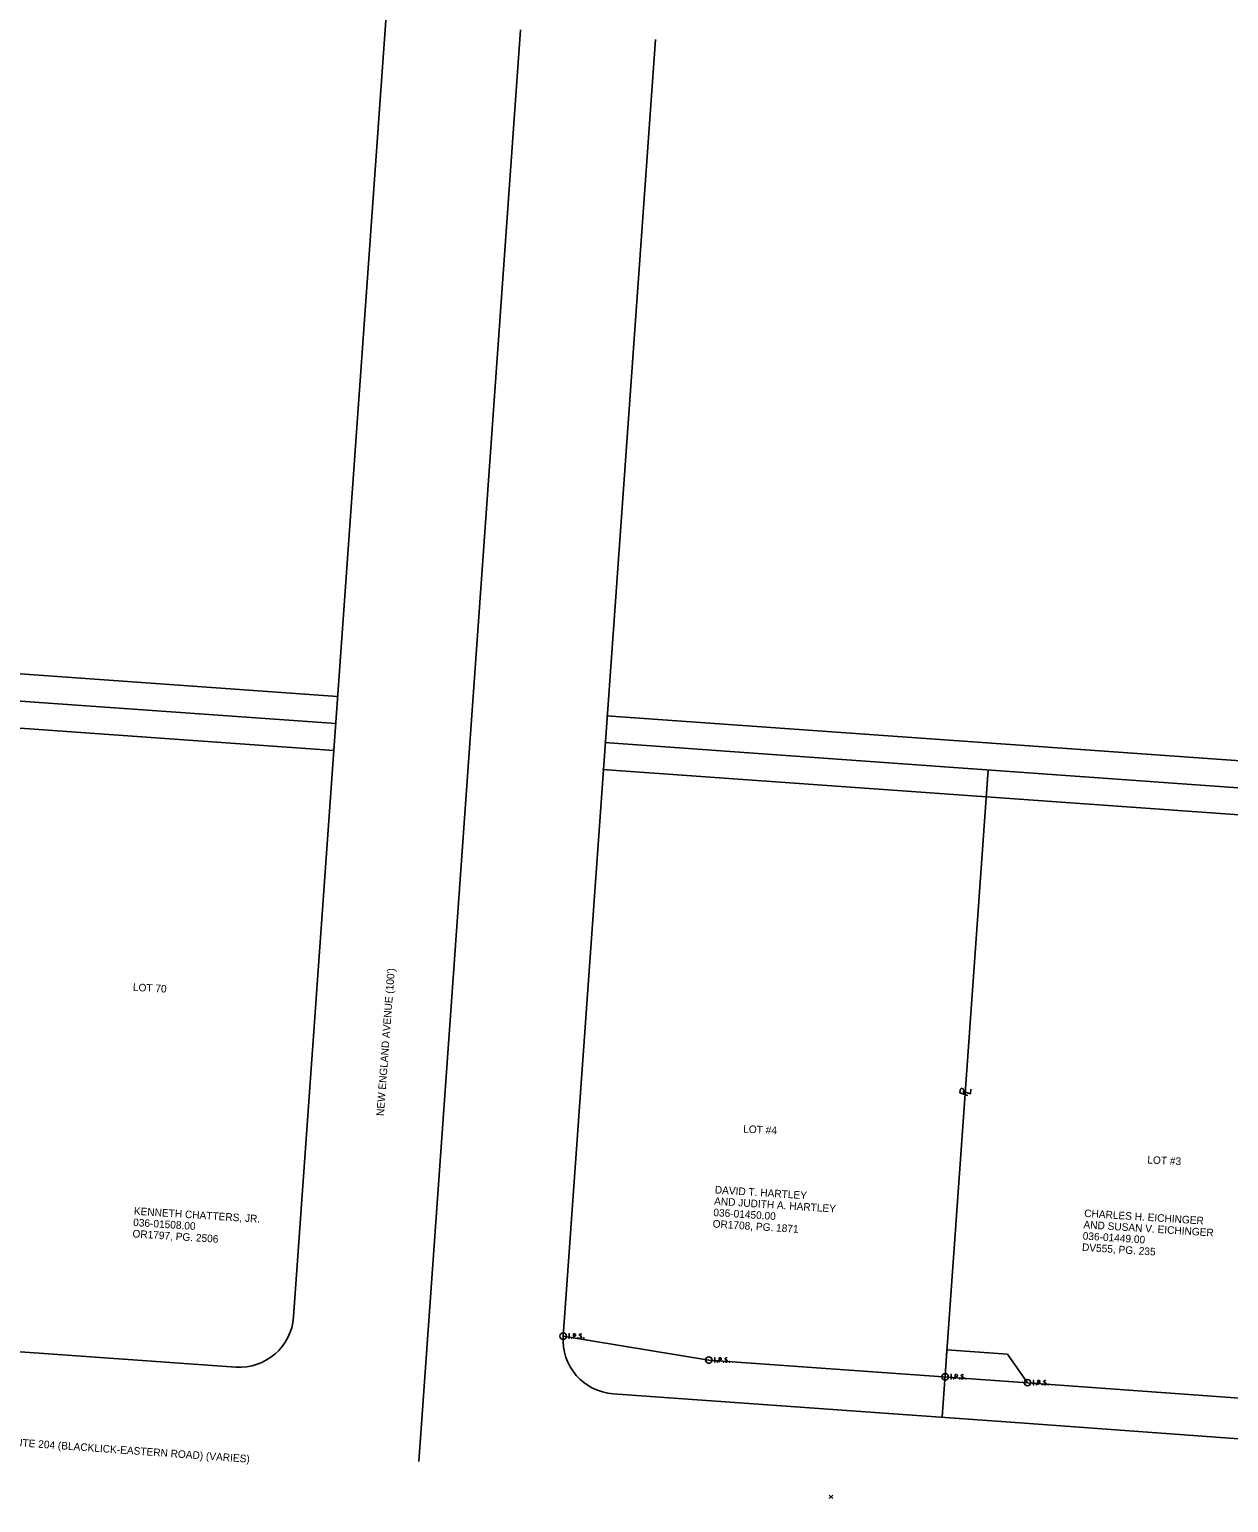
# Model space of a CAD drawing. Extents: x 1898254 to 1901377, y 701554 to 704886.
# Drawn here: x 1899450 to 1899893, y 703230 to 703775 of the extents above; entities that cross this region are included whole.
import ezdxf

# ---------------------------------------------------------------- set-up
doc = ezdxf.new("R2010")
doc.units = 0
for name, color, linetype in [('_CIVIL_CONSTRUCTION', 7, 'Continuous'), ('DV_X_Property_Line', 7, 'Continuous'), ('DV_X_Text', 7, 'Continuous'), ('PF_X_Ground_Line', 7, 'Continuous'), ('RW_X_CL', 7, 'Continuous'), ('RW_X_Esmt_U', 7, 'Continuous'), ('RW_X_Fee_RW', 7, 'Continuous'), ('RW_X_Text', 7, 'Continuous'), ('SC_Scratch2', 7, 'Continuous'), ('SC_Scratch5', 7, 'Continuous'), ('SV_P_Mon_Cells_Set', 7, 'Continuous'), ('SV_X_Random_Point', 7, 'Continuous')]:
    doc.layers.add(name, color=color, linetype=linetype)

msp = doc.modelspace()

# ---------------------------------------------------------------- linework, layer by layer
at = {"layer": '_CIVIL_CONSTRUCTION'}
msp.add_lwpolyline([(1899788.53, 703276.89), (1899789.24, 703286.86), (1899811.58, 703285.28), (1899819.04, 703274.72)], dxfattribs=at)
at = {"layer": 'DV_X_Property_Line'}
for p, q in [((1899563.1, 703518.49), (1898995.75, 703558.83)), ((1900230.14, 703471.05), (1899662.55, 703511.42)), ((1899804.49, 703501.32), (1899787.47, 703261.93)), ((1899795.34, 703381.45), (1899795.43, 703382.74)), ((1899796.02, 703382.2), (1899796.02, 703382.2))]:
    msp.add_line(p, q, dxfattribs=at)
for points in [[(1899796.9, 703380.92), (1899794, 703381.91), (1899794.07, 703382.94)], [(1899795.08, 703382.54), (1899797.98, 703381.54), (1899798.1, 703383.28)]]:
    msp.add_lwpolyline(points, dxfattribs=at)
msp.add_arc((1899794.75, 703382.79), 0.69, 356.4035, 167.2606, dxfattribs=at)
at = {"layer": 'PF_X_Ground_Line'}
msp.add_lwpolyline([(1899647.24, 703291.95), (1899701.15, 703283.1), (1899819.04, 703274.72), (1899960.56, 703264.37), (1900071.43, 703251.26), (1900129.75, 703246.99), (1900212.52, 703235.93), (1900212.15, 703230.94)], dxfattribs=at)
at = {"layer": 'RW_X_CL'}
msp.add_line((1899631.47, 703775.05), (1899593.82, 703245.62), dxfattribs=at)
at = {"layer": 'RW_X_Esmt_U'}
msp.add_line((1899188.39, 703555.16), (1899563.81, 703528.46), dxfattribs=at)
for points in [[(1899139.33, 703489.9), (1899174.08, 703536.13), (1899562.39, 703508.51)], [(1899663.26, 703521.39), (1900220.92, 703481.74), (1900223.2, 703512.15)], [(1899661.84, 703501.44), (1900219.42, 703461.79), (1900202.18, 703231.69)]]:
    msp.add_lwpolyline(points, dxfattribs=at)
at = {"layer": 'RW_X_Fee_RW'}
for p, q in [((1899547.5, 703299.04), (1899581.6, 703778.6)), ((1899681.35, 703771.51), (1899647.24, 703291.95)), ((1898630.14, 703344.22), (1899526.13, 703280.51)), ((1899665.78, 703270.58), (1899817.89, 703259.76)), ((1899817.89, 703259.76), (1900604.1, 703202.29))]:
    msp.add_line(p, q, dxfattribs=at)
for centre, start, end in [((1899527.55, 703300.46), 265.9325, 355.9325), ((1899667.19, 703290.53), 175.9325, 265.9325)]:
    msp.add_arc(centre, 20, start, end, dxfattribs=at)
at = {"layer": 'SC_Scratch2'}
msp.add_circle((1899815.76, 703229.84), 1561.35, dxfattribs=at)
at = {"layer": 'SC_Scratch5'}
for p, q in [((1899547.5, 703299.04), (1899581.6, 703778.6)), ((1899681.35, 703771.51), (1899647.24, 703291.95)), ((1898630.14, 703344.22), (1899526.13, 703280.51)), ((1899665.78, 703270.58), (1899817.89, 703259.76)), ((1899817.89, 703259.76), (1900604.1, 703202.29))]:
    msp.add_line(p, q, dxfattribs=at)
for points in [[(1899647.24, 703291.95), (1899701.15, 703283.1), (1899819.04, 703274.72), (1899960.56, 703264.37), (1900071.43, 703251.26), (1900129.75, 703246.99), (1900212.52, 703235.93), (1900212.15, 703230.94)], [(1899788.53, 703276.89), (1899789.24, 703286.86), (1899811.58, 703285.28), (1899819.04, 703274.72)]]:
    msp.add_lwpolyline(points, dxfattribs=at)
for centre, start, end in [((1899527.55, 703300.46), 265.9325, 355.9325), ((1899667.19, 703290.53), 175.9325, 265.9325)]:
    msp.add_arc(centre, 20, start, end, dxfattribs=at)
at = {"layer": 'SV_P_Mon_Cells_Set'}
for points in [[(1899649.26, 703292.75), (1899649.62, 703292.75)], [(1899649.44, 703291.15), (1899649.44, 703292.75)], [(1899651.01, 703291.15), (1899651.01, 703292.75), (1899651.53, 703292.75), (1899651.59, 703292.74), (1899651.67, 703292.71), (1899651.7, 703292.69), (1899651.73, 703292.66), (1899651.78, 703292.6), (1899651.81, 703292.54), (1899651.83, 703292.44), (1899651.83, 703292.28), (1899651.82, 703292.23), (1899651.8, 703292.16), (1899651.75, 703292.07), (1899651.71, 703292.03), (1899651.68, 703292.01), (1899651.62, 703291.98), (1899651.53, 703291.97), (1899651.01, 703291.97)], [(1899654.01, 703292.64), (1899653.99, 703292.66), (1899653.96, 703292.69), (1899653.86, 703292.73), (1899653.74, 703292.75), (1899653.65, 703292.75), (1899653.62, 703292.75), (1899653.47, 703292.71), (1899653.35, 703292.64), (1899653.28, 703292.54), (1899653.25, 703292.44), (1899653.25, 703292.36), (1899653.28, 703292.26), (1899653.36, 703292.17), (1899653.97, 703291.79), (1899654.03, 703291.74), (1899654.05, 703291.69), (1899654.07, 703291.62), (1899654.07, 703291.54), (1899654.06, 703291.47), (1899654.05, 703291.42), (1899654.03, 703291.35), (1899654, 703291.3), (1899653.98, 703291.26), (1899653.95, 703291.23), (1899653.92, 703291.2), (1899653.87, 703291.18), (1899653.84, 703291.16), (1899653.74, 703291.15), (1899653.58, 703291.15), (1899653.49, 703291.18), (1899653.34, 703291.26), (1899653.25, 703291.34)], [(1899649.26, 703291.15), (1899649.62, 703291.15)], [(1899650.4, 703291.36), (1899650.45, 703291.36), (1899650.49, 703291.34), (1899650.52, 703291.29), (1899650.52, 703291.23), (1899650.49, 703291.18), (1899650.45, 703291.15), (1899650.4, 703291.15), (1899650.37, 703291.18), (1899650.33, 703291.23), (1899650.33, 703291.29), (1899650.37, 703291.34), (1899650.4, 703291.36)], [(1899652.65, 703291.36), (1899652.7, 703291.36), (1899652.74, 703291.34), (1899652.77, 703291.29), (1899652.77, 703291.23), (1899652.74, 703291.18), (1899652.7, 703291.15), (1899652.65, 703291.15), (1899652.61, 703291.18), (1899652.58, 703291.23), (1899652.58, 703291.29), (1899652.61, 703291.34), (1899652.65, 703291.36)], [(1899654.83, 703291.36), (1899654.89, 703291.36), (1899654.92, 703291.34), (1899654.95, 703291.29), (1899654.95, 703291.23), (1899654.92, 703291.18), (1899654.89, 703291.15), (1899654.83, 703291.15), (1899654.8, 703291.18), (1899654.76, 703291.23), (1899654.76, 703291.29), (1899654.8, 703291.34), (1899654.83, 703291.36)], [(1899703.17, 703283.9), (1899703.52, 703283.9)], [(1899703.17, 703282.3), (1899703.52, 703282.3)], [(1899703.35, 703282.3), (1899703.35, 703283.9)], [(1899704.3, 703282.52), (1899704.36, 703282.52), (1899704.39, 703282.49), (1899704.43, 703282.44), (1899704.43, 703282.38), (1899704.39, 703282.33), (1899704.36, 703282.3), (1899704.3, 703282.3), (1899704.27, 703282.33), (1899704.24, 703282.38), (1899704.24, 703282.44), (1899704.27, 703282.49), (1899704.3, 703282.52)], [(1899704.91, 703282.3), (1899704.91, 703283.9), (1899705.44, 703283.9), (1899705.5, 703283.89), (1899705.57, 703283.87), (1899705.61, 703283.84), (1899705.64, 703283.82), (1899705.68, 703283.75), (1899705.72, 703283.69), (1899705.74, 703283.59), (1899705.74, 703283.44), (1899705.73, 703283.39), (1899705.7, 703283.31), (1899705.66, 703283.22), (1899705.62, 703283.19), (1899705.58, 703283.16), (1899705.53, 703283.14), (1899705.44, 703283.12), (1899704.91, 703283.12)], [(1899706.55, 703282.52), (1899706.61, 703282.52), (1899706.64, 703282.49), (1899706.67, 703282.44), (1899706.67, 703282.38), (1899706.64, 703282.33), (1899706.61, 703282.3), (1899706.55, 703282.3), (1899706.52, 703282.33), (1899706.49, 703282.38), (1899706.49, 703282.44), (1899706.52, 703282.49), (1899706.55, 703282.52)], [(1899707.92, 703283.79), (1899707.9, 703283.82), (1899707.86, 703283.84), (1899707.77, 703283.88), (1899707.64, 703283.9), (1899707.56, 703283.9), (1899707.52, 703283.9), (1899707.38, 703283.87), (1899707.26, 703283.79), (1899707.18, 703283.69), (1899707.16, 703283.59), (1899707.16, 703283.51), (1899707.18, 703283.41), (1899707.27, 703283.33), (1899707.88, 703282.95), (1899707.93, 703282.9), (1899707.95, 703282.85), (1899707.98, 703282.77), (1899707.98, 703282.7), (1899707.96, 703282.62), (1899707.95, 703282.57), (1899707.93, 703282.51), (1899707.91, 703282.46), (1899707.89, 703282.42), (1899707.85, 703282.38), (1899707.82, 703282.35), (1899707.78, 703282.33), (1899707.74, 703282.32), (1899707.64, 703282.3), (1899707.49, 703282.3), (1899707.39, 703282.33), (1899707.25, 703282.42), (1899707.16, 703282.49)], [(1899708.74, 703282.52), (1899708.79, 703282.52), (1899708.82, 703282.49), (1899708.86, 703282.44), (1899708.86, 703282.38), (1899708.82, 703282.33), (1899708.79, 703282.3), (1899708.74, 703282.3), (1899708.7, 703282.33), (1899708.67, 703282.38), (1899708.67, 703282.44), (1899708.7, 703282.49), (1899708.74, 703282.52)], [(1899790.55, 703277.69), (1899790.9, 703277.69)], [(1899790.55, 703276.09), (1899790.9, 703276.09)], [(1899790.73, 703276.09), (1899790.73, 703277.69)], [(1899791.69, 703276.3), (1899791.74, 703276.3), (1899791.77, 703276.28), (1899791.81, 703276.23), (1899791.81, 703276.17), (1899791.77, 703276.12), (1899791.74, 703276.09), (1899791.69, 703276.09), (1899791.65, 703276.12), (1899791.62, 703276.17), (1899791.62, 703276.23), (1899791.65, 703276.28), (1899791.69, 703276.3)], [(1899792.29, 703276.09), (1899792.29, 703277.69), (1899792.82, 703277.69), (1899792.88, 703277.68), (1899792.95, 703277.65), (1899792.99, 703277.63), (1899793.02, 703277.6), (1899793.06, 703277.54), (1899793.1, 703277.48), (1899793.12, 703277.38), (1899793.12, 703277.22), (1899793.11, 703277.17), (1899793.09, 703277.1), (1899793.04, 703277.01), (1899793, 703276.97), (1899792.97, 703276.95), (1899792.91, 703276.92), (1899792.82, 703276.91), (1899792.29, 703276.91)], [(1899793.94, 703276.3), (1899793.99, 703276.3), (1899794.02, 703276.28), (1899794.06, 703276.23), (1899794.06, 703276.17), (1899794.02, 703276.12), (1899793.99, 703276.09), (1899793.94, 703276.09), (1899793.9, 703276.12), (1899793.87, 703276.17), (1899793.87, 703276.23), (1899793.9, 703276.28), (1899793.94, 703276.3)], [(1899795.3, 703277.58), (1899795.28, 703277.6), (1899795.25, 703277.63), (1899795.15, 703277.67), (1899795.03, 703277.69), (1899794.94, 703277.69), (1899794.91, 703277.69), (1899794.76, 703277.65), (1899794.64, 703277.58), (1899794.56, 703277.48), (1899794.54, 703277.38), (1899794.54, 703277.3), (1899794.56, 703277.2), (1899794.65, 703277.11), (1899795.26, 703276.73), (1899795.31, 703276.68), (1899795.34, 703276.63), (1899795.36, 703276.56), (1899795.36, 703276.48), (1899795.35, 703276.41), (1899795.34, 703276.36), (1899795.31, 703276.29), (1899795.29, 703276.24), (1899795.27, 703276.2), (1899795.24, 703276.17), (1899795.2, 703276.14), (1899795.16, 703276.12), (1899795.13, 703276.1), (1899795.03, 703276.09), (1899794.87, 703276.09), (1899794.77, 703276.12), (1899794.63, 703276.2), (1899794.54, 703276.28)], [(1899796.12, 703276.3), (1899796.17, 703276.3), (1899796.21, 703276.28), (1899796.24, 703276.23), (1899796.24, 703276.17), (1899796.21, 703276.12), (1899796.17, 703276.09), (1899796.12, 703276.09), (1899796.08, 703276.12), (1899796.05, 703276.17), (1899796.05, 703276.23), (1899796.08, 703276.28), (1899796.12, 703276.3)], [(1899821.06, 703275.52), (1899821.42, 703275.52)], [(1899821.06, 703273.92), (1899821.42, 703273.92)], [(1899821.24, 703273.92), (1899821.24, 703275.52)], [(1899822.2, 703274.14), (1899822.25, 703274.14), (1899822.29, 703274.11), (1899822.32, 703274.06), (1899822.32, 703274), (1899822.29, 703273.95), (1899822.25, 703273.92), (1899822.2, 703273.92), (1899822.17, 703273.95), (1899822.13, 703274), (1899822.13, 703274.06), (1899822.17, 703274.11), (1899822.2, 703274.14)], [(1899822.8, 703273.92), (1899822.8, 703275.52), (1899823.33, 703275.52), (1899823.39, 703275.51), (1899823.47, 703275.48), (1899823.5, 703275.46), (1899823.53, 703275.43), (1899823.58, 703275.37), (1899823.61, 703275.31), (1899823.63, 703275.21), (1899823.63, 703275.05), (1899823.62, 703275), (1899823.6, 703274.93), (1899823.55, 703274.84), (1899823.51, 703274.8), (1899823.48, 703274.78), (1899823.42, 703274.75), (1899823.33, 703274.74), (1899822.8, 703274.74)], [(1899824.45, 703274.14), (1899824.5, 703274.14), (1899824.54, 703274.11), (1899824.57, 703274.06), (1899824.57, 703274), (1899824.54, 703273.95), (1899824.5, 703273.92), (1899824.45, 703273.92), (1899824.41, 703273.95), (1899824.38, 703274), (1899824.38, 703274.06), (1899824.41, 703274.11), (1899824.45, 703274.14)], [(1899825.81, 703275.41), (1899825.79, 703275.43), (1899825.76, 703275.46), (1899825.66, 703275.5), (1899825.54, 703275.52), (1899825.45, 703275.52), (1899825.42, 703275.52), (1899825.27, 703275.48), (1899825.15, 703275.41), (1899825.08, 703275.31), (1899825.05, 703275.21), (1899825.05, 703275.13), (1899825.08, 703275.03), (1899825.16, 703274.94), (1899825.77, 703274.56), (1899825.83, 703274.51), (1899825.85, 703274.46), (1899825.87, 703274.39), (1899825.87, 703274.31), (1899825.86, 703274.24), (1899825.85, 703274.19), (1899825.83, 703274.12), (1899825.8, 703274.07), (1899825.78, 703274.03), (1899825.75, 703274), (1899825.71, 703273.97), (1899825.67, 703273.95), (1899825.64, 703273.93), (1899825.54, 703273.92), (1899825.38, 703273.92), (1899825.29, 703273.95), (1899825.14, 703274.03), (1899825.05, 703274.11)], [(1899826.63, 703274.14), (1899826.68, 703274.14), (1899826.72, 703274.11), (1899826.75, 703274.06), (1899826.75, 703274), (1899826.72, 703273.95), (1899826.68, 703273.92), (1899826.63, 703273.92), (1899826.6, 703273.95), (1899826.56, 703274), (1899826.56, 703274.06), (1899826.6, 703274.11), (1899826.63, 703274.14)]]:
    msp.add_lwpolyline(points, dxfattribs=at)
for centre in [(1899647.24, 703291.95), (1899701.15, 703283.1), (1899788.53, 703276.89), (1899819.04, 703274.72)]:
    msp.add_circle(centre, 1.2, dxfattribs=at)
at = {"layer": 'SV_X_Random_Point'}
for p, q in [((1899745.66, 703231.83), (1899746.99, 703233.17)), ((1899745.66, 703233.17), (1899746.99, 703231.83))]:
    msp.add_line(p, q, dxfattribs=at)

# ---------------------------------------------------------------- texts
at = {"layer": 'DV_X_Text'}
for s, rotation, p in [("NEW ENGLAND AVENUE (100')", 85.7139, (1899580.89, 703373.26)), ('LOT 70', 357.0949, (1899488, 703419.6)), ('LOT #4', 357.0949, (1899713.79, 703367.21)), ('LOT #3', 357.0949, (1899863.3, 703355.8)), ('DAVID T. HARTLEY ', 356.3351, (1899703.28, 703344.73)), ('AND JUDITH A. HARTLEY', 356.3351, (1899703.01, 703340.53)), ('KENNETH CHATTERS, JR.', 356.3351, (1899488.35, 703336.86)), ('036-01450.00', 356.3351, (1899702.74, 703336.34)), ('CHARLES H. EICHINGER ', 356.3351, (1899839.93, 703336.04)), ('OR1797, PG. 2506', 356.3351, (1899487.82, 703328.48)), ('036-01508.00', 356.3351, (1899488.09, 703332.67)), ('OR1708, PG. 1871', 356.3351, (1899702.47, 703332.15)), ('036-01449.00', 356.3351, (1899839.39, 703327.66)), ('AND SUSAN V. EICHINGER', 356.3351, (1899839.66, 703331.85)), ('DV555, PG. 235', 356.3351, (1899839.12, 703323.47))]:
    msp.add_text(s, height=2.8, rotation=rotation, dxfattribs=at).set_placement(p)
at = {"layer": 'RW_X_Text'}
msp.add_text('STATE ROUTE 204 (BLACKLICK-EASTERN ROAD) (VARIES)', height=2.8, rotation=355.9325, dxfattribs=at).set_placement((1899425.77, 703252.61))

doc.saveas('drawing.dxf')
